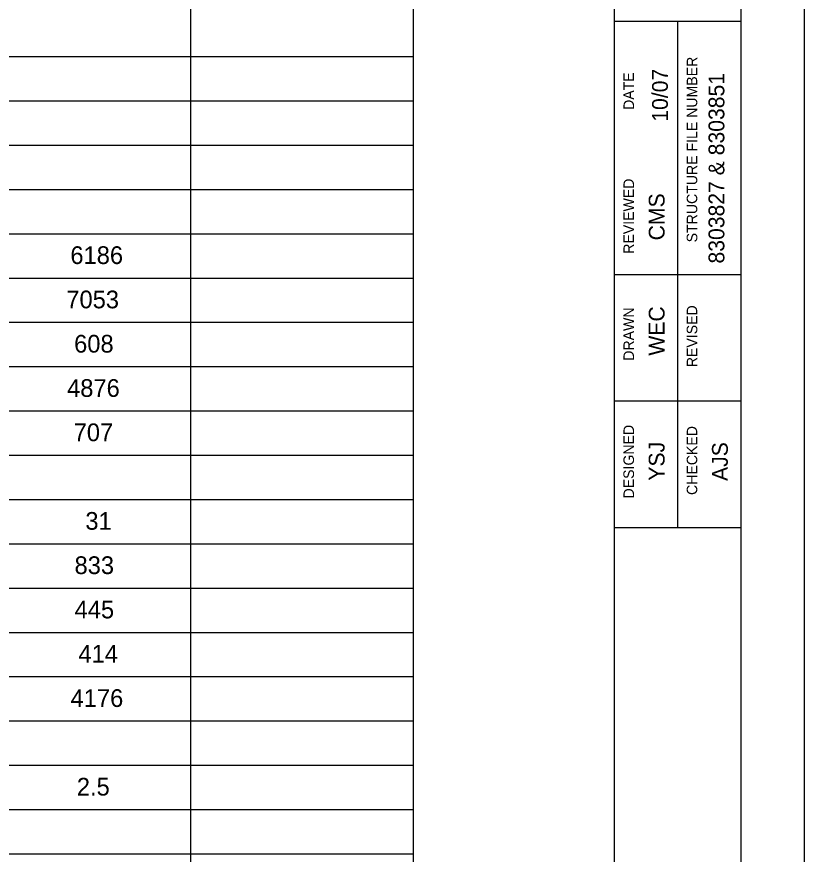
# Model space of a CAD drawing. Extents: x 0 to 34, y 0 to 22.
# Drawn here: x 27.78 to 34, y 11.42 to 18.04 of the extents above; entities that cross this region are included whole.
import ezdxf

# ---------------------------------------------------------------- set-up
doc = ezdxf.new("R2010")
doc.units = 0
for name, color, linetype in [('SH_Border', 7, 'Continuous'), ('SH_Cut_Line', 7, 'Continuous'), ('SH_Data', 7, 'Continuous'), ('SH_Text', 7, 'Continuous')]:
    doc.layers.add(name, color=color, linetype=linetype)

msp = doc.modelspace()

# ---------------------------------------------------------------- linework, layer by layer
at = {"layer": 'SH_Border'}
for p, q in [((32.5, 0.5), (32.5, 21.5)), ((32.5, 0.5), (32.5, 21.5)), ((32.5, 0.5), (32.5, 21.5)), ((32.5, 18), (33.5, 18)), ((32.5, 18), (33.5, 18)), ((32.5, 18), (33.5, 18)), ((33, 14), (33, 18)), ((33, 14), (33, 18)), ((33, 14), (33, 18)), ((32.5, 16), (33.5, 16)), ((32.5, 16), (33.5, 16)), ((32.5, 16), (33.5, 16)), ((32.5, 15), (33.5, 15)), ((32.5, 15), (33.5, 15)), ((32.5, 15), (33.5, 15)), ((32.5, 14), (33.5, 14)), ((32.5, 14), (33.5, 14)), ((32.5, 14), (33.5, 14))]:
    msp.add_line(p, q, dxfattribs=at)
msp.add_lwpolyline([(2, 21.5), (33.5, 21.5), (33.5, 0.5), (2, 0.5)], close=True, dxfattribs=at)
at = {"layer": 'SH_Cut_Line'}
msp.add_lwpolyline([(0, 22), (34, 22), (34, 0), (0, 0)], close=True, dxfattribs=at)
at = {"layer": 'SH_Text'}
for p, q in [((30.91, 20.7788), (30.91, 7.2212)), ((29.1498, 19.8212), (29.1498, 7.2212)), ((3.59, 17.7212), (30.91, 17.7212)), ((3.59, 17.3712), (30.91, 17.3712)), ((3.59, 17.0212), (30.91, 17.0212)), ((3.59, 16.6712), (30.91, 16.6712)), ((3.59, 16.3212), (30.91, 16.3212)), ((3.59, 15.9712), (30.91, 15.9712)), ((3.59, 15.6212), (30.91, 15.6212)), ((3.59, 15.2712), (30.91, 15.2712)), ((3.59, 14.9212), (30.91, 14.9212)), ((3.59, 14.5712), (30.91, 14.5712)), ((3.59, 14.2212), (30.91, 14.2212)), ((3.59, 13.8712), (30.91, 13.8712)), ((3.59, 13.5212), (30.91, 13.5212)), ((3.59, 13.1712), (30.91, 13.1712)), ((3.59, 12.8212), (30.91, 12.8212)), ((3.59, 12.4712), (30.91, 12.4712)), ((3.59, 12.1212), (30.91, 12.1212)), ((3.59, 11.7712), (30.91, 11.7712)), ((3.59, 11.4212), (30.91, 11.4212))]:
    msp.add_line(p, q, dxfattribs=at)

# ---------------------------------------------------------------- texts
at = {"layer": 'SH_Data'}
for s, height, p in [('STRUCTURE FILE NUMBER', 0.0833, (33.1542, 16.253)), ('10/07', 0.125, (32.9221, 17.206)), ('DATE', 0.0833, (32.6542, 17.2997)), ('8303827 & 8303851', 0.125, (33.3684, 16.0856)), ('REVIEWED', 0.0833, (32.6542, 16.1627)), ('CMS', 0.125, (32.8958, 16.2687)), ('REVISED', 0.0833, (33.1542, 15.2665)), ('DRAWN', 0.0833, (32.6542, 15.3177)), ('WEC', 0.125, (32.8958, 15.3576)), ('DESIGNED', 0.0833, (32.6542, 14.2292)), ('CHECKED', 0.0833, (33.1542, 14.2567)), ('YSJ', 0.125, (32.8958, 14.3699)), ('AJS', 0.125, (33.3958, 14.3675))]:
    msp.add_text(s, height=height, rotation=90, dxfattribs=at).set_placement(p)
at = {"layer": 'SH_Text'}
for s, p in [('6186', (28.1991, 16.0818)), ('7053', (28.1671, 15.7318)), ('608', (28.2288, 15.3818)), ('4876', (28.1732, 15.0318)), ('707', (28.225, 14.6818)), ('31', (28.3177, 13.9818)), ('833', (28.2321, 13.6318)), ('445', (28.2327, 13.2818)), ('414', (28.2625, 12.9318)), ('4176', (28.2008, 12.5818)), ('2.5', (28.2503, 11.8818))]:
    msp.add_text(s, height=0.14, dxfattribs=at).set_placement(p)

doc.saveas('drawing.dxf')
